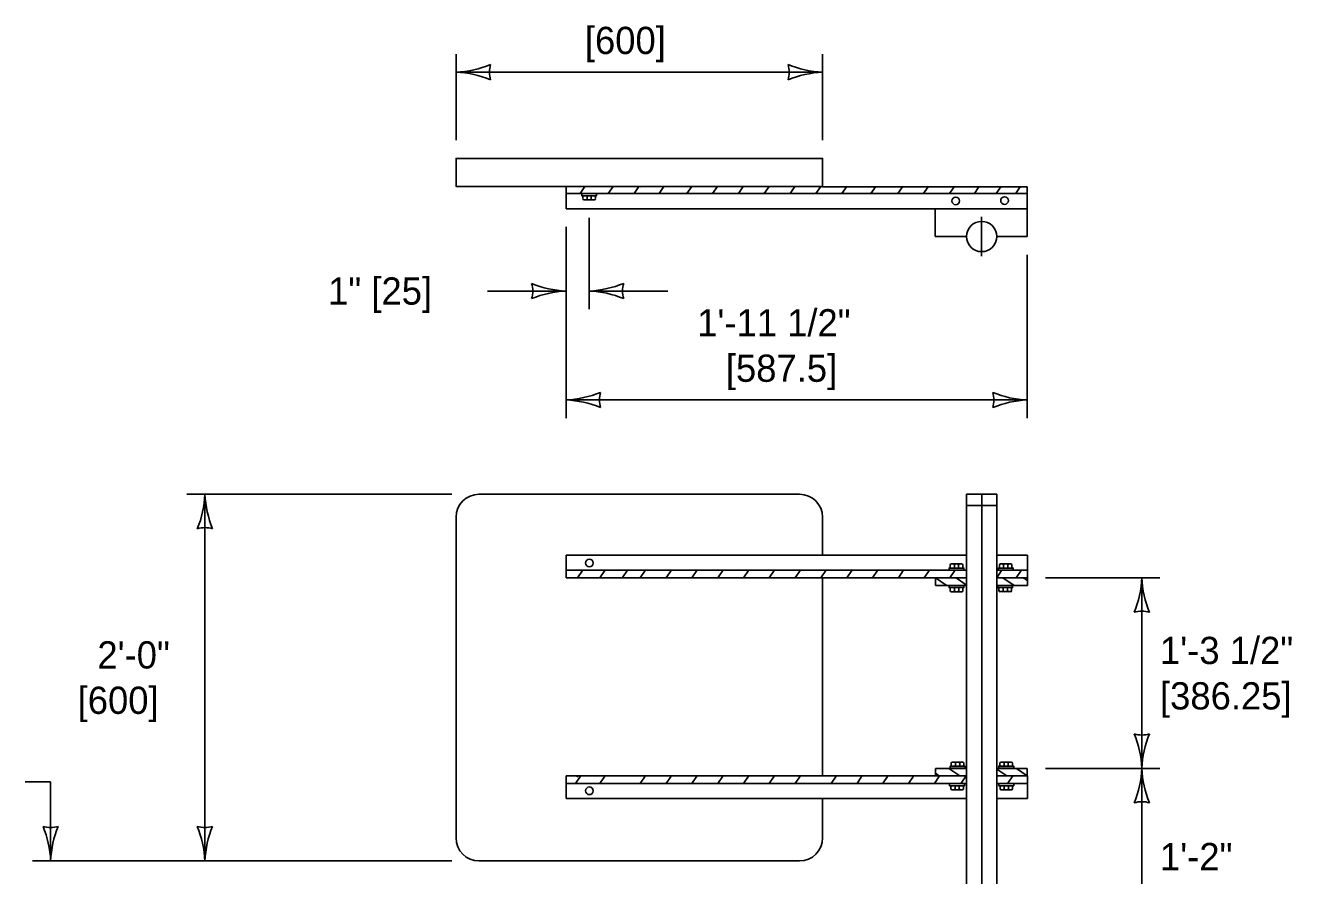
# Model space of a CAD drawing. Extents: x 49991.4 to 50021, y 49987.6 to 50011.4.
# Drawn here: x 50005.647 to 50008.437, y 49992.268 to 49994.141 of the extents above; entities that cross this region are included whole.
import ezdxf

# ---------------------------------------------------------------- set-up
doc = ezdxf.new("R2010")
doc.units = 0
for name, color, linetype in [('Level 1', 7, 'Continuous'), ('Level 2', 7, 'Continuous'), ('Level 3', 7, 'Continuous'), ('Level 4', 7, 'Continuous'), ('Level 5', 7, 'Continuous')]:
    doc.layers.add(name, color=color, linetype=linetype)

msp = doc.modelspace()

# ---------------------------------------------------------------- linework, layer by layer
at = {"layer": 'Level 1'}
for p, q in [((50006.8382, 49993.7854), (50006.8382, 49993.7369)), ((50006.8692, 49993.7701), (50006.8798, 49993.7859)), ((50006.9312, 49993.7701), (50006.9418, 49993.7859)), ((50006.988, 49993.7701), (50006.9986, 49993.7859)), ((50007.0003, 49993.7844), (50007.0015, 49993.7863)), ((50007.0431, 49993.7701), (50007.0537, 49993.7859)), ((50007.1044, 49993.7701), (50007.115, 49993.7859)), ((50007.1612, 49993.7701), (50007.1718, 49993.7859)), ((50007.2181, 49993.7701), (50007.2287, 49993.7859)), ((50007.275, 49993.7701), (50007.2856, 49993.7859)), ((50007.2846, 49993.7844), (50007.2858, 49993.7863)), ((50007.3318, 49993.7701), (50007.3424, 49993.7859)), ((50007.3887, 49993.7701), (50007.3993, 49993.7859)), ((50007.4034, 49993.7854), (50007.8544, 49993.7854)), ((50007.4462, 49993.7701), (50007.4568, 49993.7859)), ((50007.5099, 49993.7701), (50007.5205, 49993.7859)), ((50007.5691, 49993.7701), (50007.5795, 49993.7854)), ((50007.626, 49993.7701), (50007.637, 49993.7863)), ((50007.626, 49993.7701), (50007.6364, 49993.7854)), ((50007.6829, 49993.7701), (50007.6932, 49993.7854)), ((50007.738, 49993.7705), (50007.7481, 49993.7854)), ((50007.7858, 49993.7701), (50007.7962, 49993.7854)), ((50007.8288, 49993.7699), (50007.8392, 49993.7854)), ((50007.8544, 49993.7854), (50007.8544, 49993.6756)), ((50006.8382, 49993.7701), (50007.719, 49993.7701)), ((50006.8754, 49993.7591), (50006.8754, 49993.7654)), ((50006.878, 49993.7565), (50006.9006, 49993.7565)), ((50006.8846, 49993.759), (50006.8846, 49993.7654)), ((50006.8938, 49993.759), (50006.8938, 49993.7654)), ((50006.9031, 49993.7591), (50006.9031, 49993.7654)), ((50007.719, 49993.7701), (50007.8536, 49993.7701)), ((50007.7858, 49993.7701), (50007.8536, 49993.7701)), ((50006.8382, 49993.7369), (50007.6518, 49993.7369)), ((50007.6518, 49993.6756), (50007.6518, 49993.7369)), ((50007.6518, 49993.7369), (50007.7858, 49993.7369)), ((50007.7858, 49993.7369), (50007.8536, 49993.7369)), ((50007.6518, 49993.6756), (50007.7208, 49993.6756)), ((50007.7873, 49993.6756), (50007.8544, 49993.6756)), ((50006.6463, 49993.1079), (50007.3529, 49993.1079)), ((50007.7209, 49993.1079), (50007.7873, 49993.1079)), ((50007.7209, 49993.1079), (50007.721, 49988.4948)), ((50007.7209, 49993.0831), (50007.7849, 49993.0831)), ((50007.7873, 49993.1079), (50007.7873, 49988.4948)), ((50006.5958, 49992.3508), (50006.5958, 49993.0574)), ((50007.4033, 49993.0574), (50007.4034, 49992.9738)), ((50006.8381, 49992.9738), (50007.7198, 49992.9738)), ((50006.8381, 49992.9738), (50006.8381, 49992.9239)), ((50007.7872, 49992.9738), (50007.8549, 49992.9738)), ((50007.8549, 49992.9738), (50007.8549, 49992.9071)), ((50007.6847, 49992.9518), (50007.6847, 49992.9456)), ((50007.7098, 49992.9544), (50007.6872, 49992.9544)), ((50007.7099, 49992.9544), (50007.6872, 49992.9544)), ((50007.694, 49992.9544), (50007.694, 49992.9456)), ((50007.7033, 49992.9544), (50007.7033, 49992.9456)), ((50007.7124, 49992.9518), (50007.7124, 49992.9456)), ((50007.7931, 49992.9518), (50007.7931, 49992.9456)), ((50007.8181, 49992.9544), (50007.7955, 49992.9544)), ((50007.8182, 49992.9544), (50007.7955, 49992.9544)), ((50007.8023, 49992.9544), (50007.8023, 49992.9456)), ((50007.8116, 49992.9544), (50007.8116, 49992.9456)), ((50007.8207, 49992.9518), (50007.8207, 49992.9456)), ((50006.8381, 49992.9406), (50007.7204, 49992.9406)), ((50006.8381, 49992.9239), (50007.6523, 49992.9239)), ((50006.8636, 49992.9236), (50006.8745, 49992.9397)), ((50006.9124, 49992.9239), (50006.9233, 49992.94)), ((50006.9628, 49992.9249), (50006.9737, 49992.941)), ((50007.0018, 49992.9239), (50007.0127, 49992.94)), ((50007.0587, 49992.9239), (50007.0696, 49992.94)), ((50007.0683, 49992.9381), (50007.0695, 49992.94)), ((50007.1155, 49992.9239), (50007.1264, 49992.94)), ((50007.1724, 49992.9239), (50007.1833, 49992.94)), ((50007.2292, 49992.9239), (50007.2401, 49992.94)), ((50007.2861, 49992.9239), (50007.2971, 49992.94)), ((50007.343, 49992.9239), (50007.354, 49992.94)), ((50007.3526, 49992.9381), (50007.3539, 49992.94)), ((50007.3998, 49992.9239), (50007.4108, 49992.94)), ((50007.4034, 49992.9239), (50007.4034, 49992.4874)), ((50007.4567, 49992.9239), (50007.4677, 49992.94)), ((50007.5136, 49992.9239), (50007.5245, 49992.94)), ((50007.5705, 49992.9239), (50007.5814, 49992.94)), ((50007.6274, 49992.9239), (50007.6383, 49992.94)), ((50007.6523, 49992.9239), (50007.7209, 49992.9239)), ((50007.6523, 49992.9071), (50007.6523, 49992.9236)), ((50007.6761, 49992.9075), (50007.6523, 49992.9236)), ((50007.6842, 49992.9239), (50007.6951, 49992.94)), ((50007.7209, 49992.9079), (50007.6976, 49992.9237)), ((50007.7872, 49992.9406), (50007.8549, 49992.9406)), ((50007.7872, 49992.9239), (50007.7981, 49992.94)), ((50007.7872, 49992.9239), (50007.8549, 49992.9239)), ((50007.8254, 49992.907), (50007.8009, 49992.9237)), ((50007.8301, 49992.9237), (50007.841, 49992.9398)), ((50007.8549, 49992.9178), (50007.8457, 49992.924)), ((50007.6523, 49992.9071), (50007.7209, 49992.9071)), ((50007.6849, 49992.8958), (50007.6849, 49992.902)), ((50007.6874, 49992.8933), (50007.7101, 49992.8933)), ((50007.6875, 49992.8933), (50007.7101, 49992.8933)), ((50007.6941, 49992.8933), (50007.6941, 49992.902)), ((50007.7034, 49992.8933), (50007.7034, 49992.902)), ((50007.7126, 49992.8958), (50007.7126, 49992.902)), ((50007.7873, 49992.9071), (50007.8549, 49992.9071)), ((50007.7922, 49992.8959), (50007.7922, 49992.9021)), ((50007.7947, 49992.8934), (50007.8174, 49992.8934)), ((50007.7948, 49992.8934), (50007.8174, 49992.8934)), ((50007.8013, 49992.8934), (50007.8013, 49992.9021)), ((50007.8106, 49992.8934), (50007.8106, 49992.9021)), ((50007.8198, 49992.8959), (50007.8198, 49992.9021)), ((50007.652, 49992.5042), (50007.652, 49992.4875)), ((50007.7209, 49992.5042), (50007.652, 49992.5042)), ((50007.6814, 49992.5042), (50007.7059, 49992.4876)), ((50007.687, 49992.5154), (50007.687, 49992.5092)), ((50007.7121, 49992.5179), (50007.6895, 49992.5179)), ((50007.7122, 49992.5179), (50007.6895, 49992.5179)), ((50007.6962, 49992.5179), (50007.6962, 49992.5092)), ((50007.7056, 49992.5179), (50007.7056, 49992.5092)), ((50007.7147, 49992.5154), (50007.7147, 49992.5092)), ((50007.8546, 49992.5042), (50007.7873, 49992.5042)), ((50007.7873, 49992.5026), (50007.8093, 49992.4876)), ((50007.7943, 49992.5155), (50007.7943, 49992.5093)), ((50007.8194, 49992.518), (50007.7968, 49992.518)), ((50007.8195, 49992.518), (50007.7968, 49992.518)), ((50007.8035, 49992.518), (50007.8035, 49992.5093)), ((50007.8128, 49992.518), (50007.8128, 49992.5093)), ((50007.8219, 49992.5155), (50007.8219, 49992.5093)), ((50007.8308, 49992.5038), (50007.8546, 49992.4877)), ((50007.8546, 49992.5042), (50007.8546, 49992.4877)), ((50006.8381, 49992.4874), (50006.8381, 49992.4375)), ((50007.652, 49992.4874), (50006.8381, 49992.4874)), ((50007.7209, 49992.4707), (50006.8381, 49992.4707)), ((50006.8587, 49992.4706), (50006.8697, 49992.4868)), ((50006.8624, 49992.485), (50006.8637, 49992.4869)), ((50006.9124, 49992.4707), (50006.9233, 49992.4869)), ((50007.0018, 49992.4707), (50007.0127, 49992.4869)), ((50007.0587, 49992.4707), (50007.0696, 49992.4869)), ((50007.0683, 49992.485), (50007.0695, 49992.4869)), ((50007.1155, 49992.4707), (50007.1264, 49992.4869)), ((50007.1724, 49992.4707), (50007.1833, 49992.4869)), ((50007.2292, 49992.4707), (50007.2401, 49992.4869)), ((50007.2861, 49992.4707), (50007.2971, 49992.4869)), ((50007.343, 49992.4707), (50007.354, 49992.4869)), ((50007.3526, 49992.485), (50007.3539, 49992.4869)), ((50007.4225, 49992.4711), (50007.4334, 49992.4873)), ((50007.4794, 49992.471), (50007.4894, 49992.4859)), ((50007.5369, 49992.4721), (50007.5463, 49992.4861)), ((50007.5931, 49992.4711), (50007.6038, 49992.487)), ((50007.6499, 49992.4707), (50007.6611, 49992.4874)), ((50007.652, 49992.4935), (50007.6612, 49992.4873)), ((50007.7197, 49992.4874), (50007.652, 49992.4874)), ((50007.7209, 49992.4874), (50007.652, 49992.4874)), ((50007.7197, 49992.4707), (50007.652, 49992.4707)), ((50007.7197, 49992.4874), (50007.7088, 49992.4713)), ((50007.8549, 49992.4874), (50007.7873, 49992.4874)), ((50007.8549, 49992.4707), (50007.7873, 49992.4707)), ((50007.8227, 49992.4874), (50007.8118, 49992.4713)), ((50007.8549, 49992.4874), (50007.8549, 49992.4375)), ((50007.6862, 49992.4595), (50007.6862, 49992.4657)), ((50007.6886, 49992.4569), (50007.7113, 49992.4569)), ((50007.6887, 49992.4569), (50007.7113, 49992.4569)), ((50007.6953, 49992.4569), (50007.6953, 49992.4657)), ((50007.7046, 49992.4569), (50007.7046, 49992.4657)), ((50007.7138, 49992.4595), (50007.7138, 49992.4657)), ((50007.7945, 49992.4595), (50007.7945, 49992.4657)), ((50007.7969, 49992.4569), (50007.8197, 49992.4569)), ((50007.797, 49992.4569), (50007.8197, 49992.4569)), ((50007.8036, 49992.4569), (50007.8036, 49992.4657)), ((50007.8129, 49992.4569), (50007.8129, 49992.4657)), ((50007.8221, 49992.4595), (50007.8221, 49992.4657)), ((50007.7209, 49992.4375), (50006.8381, 49992.4375)), ((50007.4034, 49992.4375), (50007.4033, 49992.3508)), ((50007.8549, 49992.4375), (50007.7873, 49992.4375)), ((50007.3529, 49992.3004), (50006.6463, 49992.3004))]:
    msp.add_line(p, q, dxfattribs=at)
for points in [[(50007.4034, 49993.7859), (50007.4034, 49993.8476), (50006.5959, 49993.8476), (50006.5959, 49993.7859)], [(50006.8727, 49993.7701), (50006.8727, 49993.7654), (50006.9055, 49993.7654), (50006.9055, 49993.7701)], [(50007.7151, 49992.9408), (50007.7151, 49992.9454), (50007.6823, 49992.9454), (50007.6823, 49992.9408)], [(50007.8235, 49992.9408), (50007.8235, 49992.9454), (50007.7906, 49992.9454), (50007.7906, 49992.9408)], [(50007.6822, 49992.9069), (50007.6822, 49992.9022), (50007.7151, 49992.9022), (50007.7151, 49992.9069)], [(50007.7894, 49992.907), (50007.7894, 49992.9023), (50007.8223, 49992.9023), (50007.8223, 49992.907)], [(50007.7174, 49992.5043), (50007.7174, 49992.509), (50007.6846, 49992.509), (50007.6846, 49992.5043)], [(50007.8247, 49992.5044), (50007.8247, 49992.5091), (50007.7918, 49992.5091), (50007.7918, 49992.5044)], [(50007.6834, 49992.4705), (50007.6834, 49992.4659), (50007.7163, 49992.4659), (50007.7163, 49992.4705)], [(50007.7917, 49992.4705), (50007.7917, 49992.4659), (50007.8246, 49992.4659), (50007.8246, 49992.4705)]]:
    msp.add_lwpolyline(points, close=True, dxfattribs=at)
for centre, radius in [((50007.697, 49993.754), 0.00843), ((50007.8044, 49993.7548), 0.00843), ((50007.754, 49993.6756), 0.0333), ((50006.8896, 49992.9565), 0.00843), ((50006.8896, 49992.4547), 0.00843)]:
    msp.add_circle(centre, radius, dxfattribs=at)
for centre, radius, start, end in [((50006.878, 49993.759), 0.00257, 180, 270), ((50006.8821, 49993.759), 0.00257, 270, 0), ((50006.8872, 49993.759), 0.00257, 180, 270), ((50006.8913, 49993.759), 0.00257, 270, 0), ((50006.8964, 49993.759), 0.00257, 180, 270), ((50006.9005, 49993.759), 0.00257, 270, 0), ((50006.6463, 49993.0574), 0.0505, 90, 180), ((50007.3529, 49993.0574), 0.0505, 0, 90), ((50007.6873, 49992.9518), 0.00257, 90, 180), ((50007.6914, 49992.9518), 0.00257, 0, 90), ((50007.6965, 49992.9518), 0.00257, 90, 180), ((50007.7006, 49992.9518), 0.00257, 0, 90), ((50007.7057, 49992.9518), 0.00257, 90, 180), ((50007.7098, 49992.9518), 0.00257, 0, 90), ((50007.7956, 49992.9518), 0.00257, 90, 180), ((50007.7997, 49992.9518), 0.00257, 0, 90), ((50007.8048, 49992.9518), 0.00257, 90, 180), ((50007.8089, 49992.9518), 0.00257, 0, 90), ((50007.814, 49992.9518), 0.00257, 90, 180), ((50007.8181, 49992.9518), 0.00257, 0, 90), ((50007.6875, 49992.8958), 0.00257, 180, 270), ((50007.6916, 49992.8958), 0.00257, 270, 0), ((50007.6967, 49992.8958), 0.00257, 180, 270), ((50007.7008, 49992.8958), 0.00257, 270, 0), ((50007.7059, 49992.8958), 0.00257, 180, 270), ((50007.71, 49992.8958), 0.00257, 270, 0), ((50007.7948, 49992.8959), 0.00257, 180, 270), ((50007.7988, 49992.8959), 0.00257, 270, 0), ((50007.804, 49992.8959), 0.00257, 180, 270), ((50007.8081, 49992.8959), 0.00257, 270, 0), ((50007.8132, 49992.8959), 0.00257, 180, 270), ((50007.8173, 49992.8959), 0.00257, 270, 0), ((50007.6896, 49992.5154), 0.00257, 90, 180), ((50007.6937, 49992.5154), 0.00257, 0, 90), ((50007.6988, 49992.5154), 0.00257, 90, 180), ((50007.7029, 49992.5154), 0.00257, 0, 90), ((50007.708, 49992.5154), 0.00257, 90, 180), ((50007.7121, 49992.5154), 0.00257, 0, 90), ((50007.7969, 49992.5155), 0.00257, 90, 180), ((50007.8009, 49992.5155), 0.00257, 0, 90), ((50007.8061, 49992.5155), 0.00257, 90, 180), ((50007.8101, 49992.5155), 0.00257, 0, 90), ((50007.8153, 49992.5155), 0.00257, 90, 180), ((50007.8193, 49992.5155), 0.00257, 0, 90), ((50007.6888, 49992.4595), 0.00257, 180, 270), ((50007.6928, 49992.4595), 0.00257, 270, 0), ((50007.698, 49992.4595), 0.00257, 180, 270), ((50007.702, 49992.4595), 0.00257, 270, 0), ((50007.7072, 49992.4595), 0.00257, 180, 270), ((50007.7112, 49992.4595), 0.00257, 270, 0), ((50007.7971, 49992.4595), 0.00257, 180, 270), ((50007.8011, 49992.4595), 0.00257, 270, 0), ((50007.8063, 49992.4595), 0.00257, 180, 270), ((50007.8103, 49992.4595), 0.00257, 270, 0), ((50007.8155, 49992.4595), 0.00257, 180, 270), ((50007.8195, 49992.4595), 0.00257, 270, 0), ((50006.6463, 49992.3508), 0.0505, 180, 270), ((50007.3529, 49992.3508), 0.0505, 270, 0)]:
    msp.add_arc(centre, radius, start, end, dxfattribs=at)
at = {"layer": 'Level 3'}
for p, q in [((50006.5959, 49993.8876), (50006.5959, 49994.0776)), ((50007.4034, 49993.8876), (50007.4034, 49994.0776)), ((50006.5959, 49994.0376), (50007.4034, 49994.0376)), ((50006.8382, 49993.2756), (50006.8382, 49993.6969)), ((50006.8893, 49993.5156), (50006.8893, 49993.7165)), ((50007.8544, 49993.2756), (50007.8544, 49993.6356)), ((50006.6648, 49993.5556), (50006.8382, 49993.5556)), ((50006.8893, 49993.5556), (50007.0627, 49993.5556)), ((50006.8382, 49993.3156), (50007.8544, 49993.3156)), ((50006.0024, 49993.1079), (50006.5863, 49993.1079)), ((50006.0424, 49992.3004), (50006.0424, 49993.1079)), ((50007.8949, 49992.9239), (50008.147, 49992.9239)), ((50008.107, 49992.9239), (50008.107, 49992.5042)), ((50007.8946, 49992.5042), (50008.147, 49992.5042)), ((50008.107, 49992.0155), (50008.107, 49992.5042)), ((50005.6466, 49992.4743), (50005.7024, 49992.4743)), ((50005.7024, 49992.3009), (50005.7024, 49992.4743)), ((50005.6624, 49992.3004), (50006.5863, 49992.3004))]:
    msp.add_line(p, q, dxfattribs=at)
for centre, radius, start, end in [((50006.5844, 49994.2703), 0.233, 272.8273, 292.0772), ((50006.5867, 49993.8155), 0.2223, 67.456, 87.6395), ((50006.7241, 49994.0376), 0.0548, 162.1388, 197.8612), ((50007.4126, 49994.2597), 0.2223, 247.456, 267.6395), ((50007.2752, 49994.0376), 0.0548, 342.1388, 17.8612), ((50007.4149, 49993.8049), 0.233, 92.8273, 112.0772), ((50006.8474, 49993.7777), 0.2223, 247.456, 267.6395), ((50006.71, 49993.5556), 0.0548, 342.1388, 17.8612), ((50006.8497, 49993.3229), 0.233, 92.8273, 112.0772), ((50006.8778, 49993.7883), 0.233, 272.8273, 292.0772), ((50006.8801, 49993.3335), 0.2223, 67.456, 87.6395), ((50007.0175, 49993.5556), 0.0548, 162.1388, 197.8612), ((50006.8267, 49993.5483), 0.233, 272.8273, 292.0772), ((50006.9664, 49993.3156), 0.0548, 162.1388, 197.8612), ((50007.8636, 49993.5377), 0.2223, 247.456, 267.6395), ((50007.7262, 49993.3156), 0.0548, 342.1388, 17.8612), ((50006.829, 49993.0935), 0.2223, 67.456, 87.6395), ((50007.8659, 49993.0829), 0.233, 92.8273, 112.0772), ((50005.8203, 49993.1171), 0.2223, 337.456, 357.6395), ((50006.2751, 49993.1194), 0.233, 182.8273, 202.0772), ((50006.0424, 49992.9797), 0.0548, 72.1388, 107.8612), ((50007.8849, 49992.9331), 0.2223, 337.456, 357.6395), ((50008.3397, 49992.9354), 0.233, 182.8273, 202.0772), ((50008.107, 49992.7957), 0.0548, 72.1388, 107.8612), ((50008.107, 49992.6324), 0.0548, 252.1388, 287.8612), ((50007.8743, 49992.4927), 0.233, 2.8273, 22.0772), ((50008.3291, 49992.495), 0.2223, 157.456, 177.6395), ((50007.8849, 49992.5134), 0.2223, 337.456, 357.6395), ((50008.3397, 49992.5157), 0.233, 182.8273, 202.0772), ((50008.107, 49992.376), 0.0548, 72.1388, 107.8612), ((50005.7024, 49992.4286), 0.0548, 252.1388, 287.8612), ((50005.4697, 49992.2889), 0.233, 2.8273, 22.0772), ((50005.9245, 49992.2912), 0.2223, 157.456, 177.6395), ((50006.0424, 49992.4286), 0.0548, 252.1388, 287.8612), ((50005.8097, 49992.2889), 0.233, 2.8273, 22.0772), ((50006.2645, 49992.2912), 0.2223, 157.456, 177.6395)]:
    msp.add_arc(centre, radius, start, end, dxfattribs=at)
at = {"layer": 'Level 4'}
msp.add_line((50007.7541, 49993.1079), (50007.7541, 49990.2553), dxfattribs=at)
at = {"layer": 'Level 5'}
msp.add_line((50007.7539, 49993.7189), (50007.7539, 49993.6324), dxfattribs=at)

# ---------------------------------------------------------------- texts
at = {"layer": 'Level 2'}
for s, p in [('[600]', (50006.8796, 49994.0776)), ('1" [25]', (50006.3137, 49993.5256)), ('1\'-11 1/2"', (50007.1271, 49993.4556)), ('[587.5]', (50007.1903, 49993.3556)), ('2\'-0"', (50005.8054, 49992.7241)), ('1\'-3 1/2"', (50008.147, 49992.7339)), ('[386.25]', (50008.147, 49992.6339)), ('[600]', (50005.7619, 49992.6241)), ('1\'-2"', (50008.147, 49992.2799))]:
    msp.add_text(s, height=0.06, dxfattribs=at).set_placement(p)

doc.saveas('drawing.dxf')
